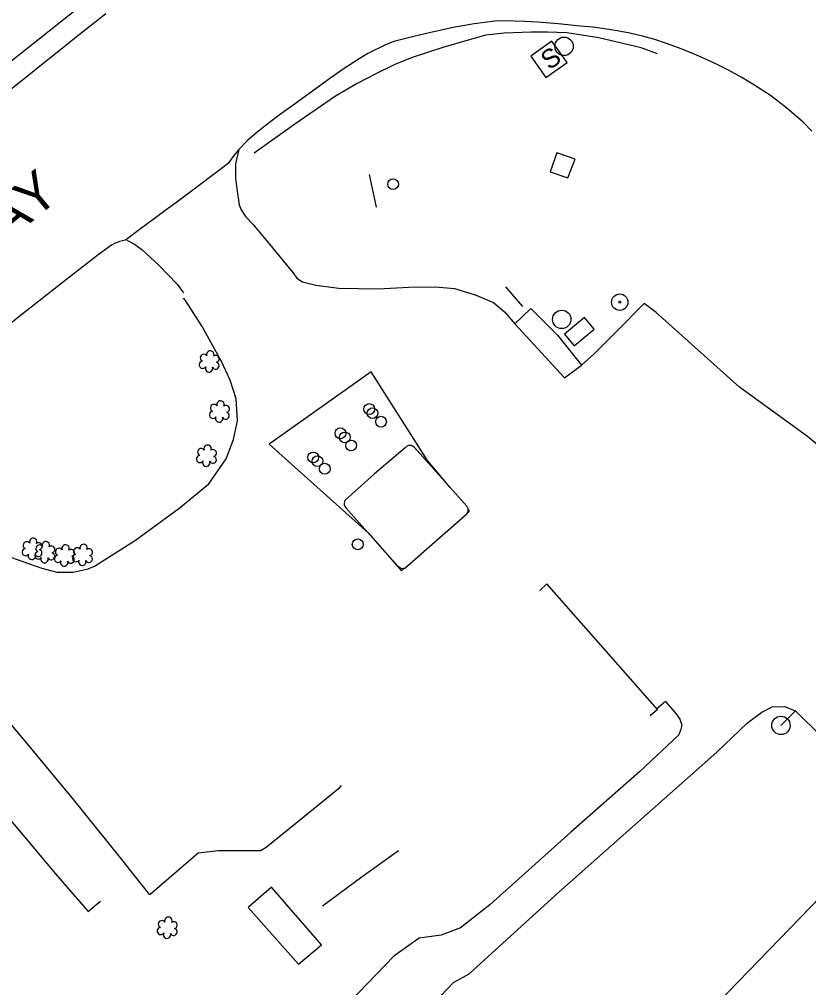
# Model space of a CAD drawing. Extents: x 471894 to 476235, y 503501 to 507878.
# Drawn here: x 473515.9 to 473726.4, y 505870.1 to 506128.6 of the extents above; entities that cross this region are included whole.
import ezdxf

# ---------------------------------------------------------------- set-up
doc = ezdxf.new("R2010")
doc.units = 0
for name, color, linetype in [('Exist Building Metal Canopy', 7, 'Continuous'), ('Exist Guardrail', 7, 'Continuous'), ('Exist Horizontal Alignment', 7, 'Continuous'), ('Exist Other Culture AG Tank', 7, 'Continuous'), ('Exist Other Culture Area Outline', 7, 'Continuous'), ('Exist Other Culture Fence Line', 7, 'Continuous'), ('Exist Other Culture Gas Pump or Vent CELL', 7, 'Continuous'), ('Exist Other Culture Sign', 7, 'Continuous'), ('Exist Other Culture Sign Post CELL', 7, 'Continuous'), ('Exist Roads Change in Surface', 7, 'Continuous'), ('Exist Roads Curbs', 7, 'Continuous'), ('Exist Roads EOP', 7, 'Continuous'), ('Exist Roads EOP Other', 7, 'Continuous'), ('Exist Roads EOP Text', 7, 'Continuous'), ('Exist Utilities Other Pole CELL', 7, 'Continuous'), ('Exist Utilities Other Traffic Signal Box CELL', 7, 'Continuous'), ('Exist Utilities Power Pole CELL', 7, 'Continuous'), ('Exist Vegetation Shrub CELL', 7, 'Continuous')]:
    doc.layers.add(name, color=color, linetype=linetype)

msp = doc.modelspace()

# ---------------------------------------------------------------- linework, layer by layer
at = {"layer": 'Exist Building Metal Canopy'}
msp.add_lwpolyline([(473610.59, 506007.31), (473602.64, 506000.13), (473602.48, 505999.44), (473602.53, 505998.87), (473602.98, 505998.15), (473616.85, 505982.62), (473617.76, 505982.04), (473618.26, 505982.05), (473618.7, 505982.13), (473635.22, 505996.57), (473635.61, 505997.31), (473635.55, 505997.97), (473635.21, 505998.6), (473621.24, 506014.27), (473620.49, 506014.85), (473619.65, 506014.83), (473619.24, 506014.62), (473618.78, 506014.24), (473610.59, 506007.31)], dxfattribs=at)
msp.add_lwpolyline([(473576.89, 505891.5), (473590.34, 505876.41), (473596.47, 505881.61), (473583.09, 505896.99)], close=True, dxfattribs=at)
at = {"layer": 'Exist Guardrail'}
msp.add_lwpolyline([(473686.12, 506119.38), (473681.73, 506120.93), (473670.41, 506123.61), (473661.87, 506124.93), (473656.72, 506125.12), (473652.41, 506125.18), (473645.16, 506124.91), (473640.23, 506124.34), (473628.8, 506121.02), (473620.65, 506118.35), (473616.04, 506116.48), (473610.77, 506113.91), (473605.95, 506111.41), (473600.22, 506108.05), (473589.32, 506100.59), (473578.49, 506092.86)], dxfattribs=at)
at = {"layer": 'Exist Horizontal Alignment'}
msp.add_line((473294.53, 505943.19), (474190.95, 506656.19), dxfattribs=at)
at = {"layer": 'Exist Other Culture AG Tank'}
msp.add_lwpolyline([(473666.62, 506048.98), (473661.26, 506044.54), (473663.84, 506041.43), (473669.2, 506045.87)], close=True, dxfattribs=at)
at = {"layer": 'Exist Other Culture Area Outline'}
msp.add_lwpolyline([(473648.01, 506047.32), (473652.31, 506051.39), (473659.46, 506044.28), (473665.82, 506036.28)], dxfattribs=at)
at = {"layer": 'Exist Other Culture Fence Line'}
msp.add_lwpolyline([(473596.74, 505892.01), (473607.28, 505899.8), (473617.03, 505906.72)], dxfattribs=at)
at = {"layer": 'Exist Other Culture Gas Pump or Vent CELL'}
for centre in [(473615.55, 506084.57), (473609.18, 506024.56), (473610.06, 506023.46), (473612.33, 506021.18), (473601.5, 506018.09), (473602.69, 506016.99), (473604.36, 506014.84), (473594.25, 506011.65), (473595.37, 506010.65), (473597.32, 506008.63), (473606.12, 505988.45)]:
    msp.add_circle(centre, 1.44, dxfattribs=at)
at = {"layer": 'Exist Other Culture Sign'}
for p, q in [((473609.18, 506087.18), (473611.03, 506078.42)), ((473645.55, 506057.14), (473650.04, 506051.92))]:
    msp.add_line(p, q, dxfattribs=at)
at = {"layer": 'Exist Other Culture Sign Post CELL'}
for radius in [2.18, 0.24]:
    msp.add_circle((473676.03, 506053.08), radius, dxfattribs=at)
at = {"layer": 'Exist Roads Change in Surface'}
for points in [[(473630.77, 506003.58), (473624.77, 506010.84), (473609.69, 506034.48), (473582.52, 506015.22)], [(473582.52, 506015.22), (473608.95, 505991.5), (473617.8, 505981.42), (473618.59, 505982.11)], [(473635.28, 505996.68), (473635.98, 505997.29), (473635.57, 505997.78)]]:
    msp.add_lwpolyline(points, dxfattribs=at)
at = {"layer": 'Exist Roads Curbs'}
msp.add_line((473686.08, 505944.39), (473684.17, 505942.66), dxfattribs=at)
msp.add_lwpolyline([(473686.08, 505944.39), (473656.61, 505977.89), (473654.68, 505976.14)], dxfattribs=at)
at = {"layer": 'Exist Roads EOP'}
for points in [[(473513.65, 506110.04), (473517.89, 506113.42), (473522.15, 506116.81), (473526.39, 506120.18), (473530.6, 506123.53), (473534.78, 506126.86), (473538.9, 506130.14)], [(473727.25, 506098.75), (473725.07, 506101.03), (473720.61, 506104.85), (473716.2, 506108.2), (473711.53, 506111.29), (473708.43, 506113.12), (473705.07, 506114.97), (473701.82, 506116.6), (473698.54, 506118.11), (473695.09, 506119.58), (473691.68, 506120.95), (473688.52, 506122.13), (473685.4, 506123.16), (473682.11, 506124.07), (473678.73, 506124.84), (473675.3, 506125.5), (473671.96, 506126.03), (473668.8, 506126.43), (473665.51, 506126.78), (473659.58, 506127.37), (473654.04, 506127.76), (473650.69, 506127.95), (473644.78, 506128.14), (473642.7, 506128.09), (473637.2, 506127.32), (473634.15, 506126.81), (473631.13, 506126.26), (473625.64, 506125.07), (473621.07, 506123.95), (473615.73, 506122.62), (473613.33, 506121.71), (473608.81, 506119.41), (473606.47, 506118.05), (473601.99, 506115.11), (473598.31, 506112.52), (473594.02, 506109.41), (473589.51, 506106.11), (473585.2, 506102.95), (473581.46, 506100.15), (473578.71, 506097.93), (473576.74, 506096.19), (473574.34, 506093.72), (473572.51, 506091.49), (473571.55, 506090.1), (473567.53, 506087.04), (473563.9, 506084.31), (473560.68, 506081.89), (473557.85, 506079.79), (473555.02, 506077.7), (473551.8, 506075.31), (473548.19, 506072.63), (473544.18, 506069.65), (473542.58, 506069.24), (473541.94, 506069.03), (473541.41, 506068.8), (473540.4, 506068.25), (473536.9, 506065.72), (473534.79, 506064.1), (473532.07, 506061.99), (473528.84, 506059.46), (473525.17, 506056.58), (473521.06, 506053.34), (473516.52, 506049.76), (473511.73, 506045.94)]]:
    msp.add_lwpolyline(points, dxfattribs=at)
at = {"layer": 'Exist Roads EOP Other'}
msp.add_line((473662.16, 506086.22), (473664.15, 506091.22), dxfattribs=at)
for points in [[(473574.43, 506093.83), (473573.53, 506089.98), (473573.53, 506086.14), (473573.85, 506083.31), (473574.45, 506079.05), (473575.06, 506077.74), (473576.18, 506075.94), (473578.12, 506073.86), (473582.62, 506068.54), (473587.01, 506063.15), (473588.88, 506060.93), (473589.87, 506059.51), (473591.42, 506058.53), (473594.96, 506057.64), (473601.07, 506056.86), (473611.56, 506056.65), (473619.73, 506057.04), (473626.91, 506057.17), (473631.93, 506056.7), (473637.46, 506055.01), (473642.36, 506052.97), (473645.32, 506050.53), (473648.01, 506047.32), (473661.31, 506032.88), (473665.82, 506036.28)], [(473664.15, 506091.22), (473659.2, 506092.97), (473657.43, 506087.84), (473662.16, 506086.22)], [(473544.54, 506069.59), (473546.55, 506068.52), (473548.52, 506067.15), (473553.06, 506062.97), (473557.93, 506057.88), (473559.65, 506055.61)], [(473493.13, 506001.43), (473493.26, 506001.2), (473496.33, 505997.78), (473502.67, 505991.42), (473507.66, 505987.79), (473512.21, 505985.44), (473516.74, 505983.83), (473521.86, 505982.08), (473525.83, 505981.06), (473530.24, 505981.01), (473534.22, 505981.89), (473535.87, 505982.61), (473546.81, 505989.6), (473558.42, 505998.01), (473566.41, 506004.61), (473571.04, 506011.27), (473572.95, 506016.44), (473574.02, 506021.38), (473573.68, 506027.3), (473572.12, 506032.3), (473569.74, 506037.25), (473564.61, 506046.56), (473560.16, 506053.55), (473559.67, 506054.15)], [(473804.1, 505977.12), (473803.9, 505977.06), (473799.7, 505976.69), (473789.56, 505976.67), (473778.14, 505974.45), (473773.59, 505973.52), (473770.1, 505973.29), (473768.28, 505974.3), (473766.48, 505975.83), (473765.34, 505977.91), (473765.4, 505979.74), (473767.08, 505982.97), (473755.99, 505992.41), (473741.7, 506004.2), (473726.1, 506017.21), (473707.96, 506030.39), (473685.74, 506050.29), (473682.56, 506052.7), (473675.11, 506045.13), (473669.11, 506039.17), (473665.82, 506036.28)], [(473601.74, 505924.05), (473600.97, 505923.23), (473591.48, 505915.5), (473581.7, 505907.53), (473580.14, 505906.66), (473568.96, 505906.64), (473563.56, 505906.02), (473550.68, 505894.94), (473542.79, 505904.77), (473530.38, 505920.26), (473517.96, 505935.3), (473501.3, 505955.07), (473491.52, 505963.44), (473474.89, 505976.36), (473468.32, 505980.84), (473468.22, 505980.87)], [(473688.26, 505946.52), (473690.97, 505943.27), (473692.06, 505941.76), (473692.56, 505940.23), (473692.34, 505939.15), (473691.77, 505937.65), (473681.42, 505927.79), (473662.99, 505911.61), (473641.38, 505892.22), (473633.51, 505886.14), (473628.41, 505884.17), (473622.48, 505883.37), (473615.73, 505878.53), (473601.76, 505864.08)], [(473623.17, 505862.54), (473631.67, 505871.55), (473635.86, 505873.86), (473659.81, 505895.65), (473701.95, 505932.97), (473710.11, 505940.82), (473713.9, 505943.62), (473716.67, 505945.1), (473720.03, 505945.14), (473723.01, 505943.95), (473737.02, 505930.05), (473750.05, 505916.76)], [(473688.26, 505946.52), (473685.94, 505944.55)], [(473411.45, 505935.47), (473412.43, 505934.08), (473422.07, 505920.56), (473429.34, 505910.54), (473430.86, 505908.64), (473439.92, 505913.62), (473451.81, 505920.61), (473462.33, 505927.79), (473478.22, 505938.6), (473489.57, 505922.5), (473494.35, 505915.27), (473506.55, 505923.04), (473525.49, 505900.55), (473534.23, 505890.49), (473536.11, 505892.11), (473537.51, 505893.23)], [(473685.49, 505848.83), (473735.17, 505900.17), (473750.05, 505916.76)]]:
    msp.add_lwpolyline(points, dxfattribs=at)
at = {"layer": 'Exist Utilities Other Pole CELL'}
for centre in [(473661.18, 506121.36), (473660.55, 506048.49)]:
    msp.add_circle(centre, 2.46, dxfattribs=at)
at = {"layer": 'Exist Utilities Other Traffic Signal Box CELL'}
msp.add_line((473657.12, 506117.88), (473657.12, 506117.88), dxfattribs=at)
msp.add_lwpolyline([(473656.31, 506113.03), (473661.97, 506117.06), (473657.94, 506122.73), (473652.28, 506118.69), (473656.31, 506113.03)], dxfattribs=at)
at = {"layer": 'Exist Utilities Power Pole CELL'}
for q in [(473723.03, 505944.09), (473719.04, 505940.13)]:
    msp.add_line((473719.04, 505940.13), q, dxfattribs=at)
msp.add_circle((473719.04, 505940.13), 2.45, dxfattribs=at)
at = {"layer": 'Exist Vegetation Shrub CELL'}
for p, q in [((473566.57, 506037.07), (473566.57, 506037.07)), ((473569.28, 506023.72), (473569.28, 506023.72)), ((473565.85, 506011.93), (473565.85, 506011.93)), ((473519.31, 505987.07), (473519.31, 505987.07)), ((473522.7, 505986.18), (473522.7, 505986.18)), ((473532.76, 505985.46), (473532.76, 505985.46)), ((473527.93, 505985.3), (473527.93, 505985.3)), ((473555.37, 505885.95), (473555.37, 505885.95))]:
    msp.add_line(p, q, dxfattribs=at)
for centre, radius, start, end in [((473566.8, 506039.11), 0.99, 334.8391, 200.4717), ((473564.77, 506036.36), 0.955, 95.1099, 327.9534), ((473565.08, 506038.2), 0.968, 35.8908, 245.4216), ((473568.2, 506036.14), 0.937, 204.9913, 73.4601), ((473568.24, 506037.94), 0.929, 284.4567, 126.0861), ((473566.44, 506035.39), 0.984, 151.2797, 21.387), ((473569.51, 506025.76), 0.99, 334.8391, 200.4717), ((473567.8, 506024.85), 0.968, 35.8908, 245.4216), ((473570.95, 506024.59), 0.929, 284.4567, 126.0861), ((473567.48, 506023.02), 0.955, 95.1099, 327.9534), ((473569.15, 506022.04), 0.984, 151.2797, 21.387), ((473570.92, 506022.79), 0.937, 204.9913, 73.4601), ((473564.37, 506013.06), 0.968, 35.8908, 245.4216), ((473566.08, 506013.97), 0.99, 334.8391, 200.4717), ((473564.05, 506011.23), 0.955, 95.1099, 327.9534), ((473567.49, 506011), 0.937, 204.9913, 73.4601), ((473567.52, 506012.8), 0.929, 284.4567, 126.0861), ((473565.72, 506010.25), 0.984, 151.2797, 21.387), ((473517.83, 505988.19), 0.968, 35.8908, 245.4216), ((473519.54, 505989.11), 0.99, 334.8391, 200.4717), ((473521.22, 505987.31), 0.968, 35.8908, 245.4216), ((473520.98, 505987.94), 0.929, 284.4567, 126.0861), ((473522.93, 505988.22), 0.99, 334.8391, 200.4717), ((473524.37, 505987.05), 0.929, 284.4567, 126.0861), ((473528.16, 505987.34), 0.99, 334.8391, 200.4717), ((473532.98, 505987.5), 0.99, 334.8391, 200.4717), ((473517.51, 505986.36), 0.955, 95.1099, 327.9534), ((473519.18, 505985.38), 0.984, 151.2797, 21.387), ((473520.9, 505985.48), 0.955, 95.1099, 327.9534), ((473520.95, 505986.14), 0.937, 204.9913, 73.4601), ((473524.34, 505985.25), 0.937, 204.9913, 73.4601), ((473526.13, 505984.59), 0.955, 95.1099, 327.9534), ((473526.44, 505986.42), 0.968, 35.8908, 245.4216), ((473529.6, 505986.17), 0.929, 284.4567, 126.0861), ((473530.96, 505984.75), 0.955, 95.1099, 327.9534), ((473531.27, 505986.59), 0.968, 35.8908, 245.4216), ((473534.39, 505984.53), 0.937, 204.9913, 73.4601), ((473534.43, 505986.33), 0.929, 284.4567, 126.0861), ((473522.57, 505984.5), 0.984, 151.2797, 21.387), ((473527.8, 505983.61), 0.984, 151.2797, 21.387), ((473529.56, 505984.37), 0.937, 204.9913, 73.4601), ((473532.63, 505983.77), 0.984, 151.2797, 21.387), ((473553.89, 505887.08), 0.968, 35.8908, 245.4216), ((473555.6, 505887.99), 0.99, 334.8391, 200.4717), ((473557.04, 505886.82), 0.929, 284.4567, 126.0861), ((473553.57, 505885.25), 0.955, 95.1099, 327.9534), ((473555.24, 505884.27), 0.984, 151.2797, 21.387), ((473557.01, 505885.02), 0.937, 204.9913, 73.4601)]:
    msp.add_arc(centre, radius, start, end, dxfattribs=at)

# ---------------------------------------------------------------- texts
at = {"layer": 'Exist Roads EOP Text'}
msp.add_text("US 64/74 42' PAVED ROADWAY", height=10.4, rotation=39.7704, dxfattribs=at).set_placement((473368.17, 505948.77))
at = {"layer": 'Exist Utilities Other Traffic Signal Box CELL'}
msp.add_text('S', height=5, rotation=35.4521, dxfattribs=at).set_placement((473657.24, 506114.89))

doc.saveas('drawing.dxf')
